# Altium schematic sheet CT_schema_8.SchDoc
size 401 x 301 mm
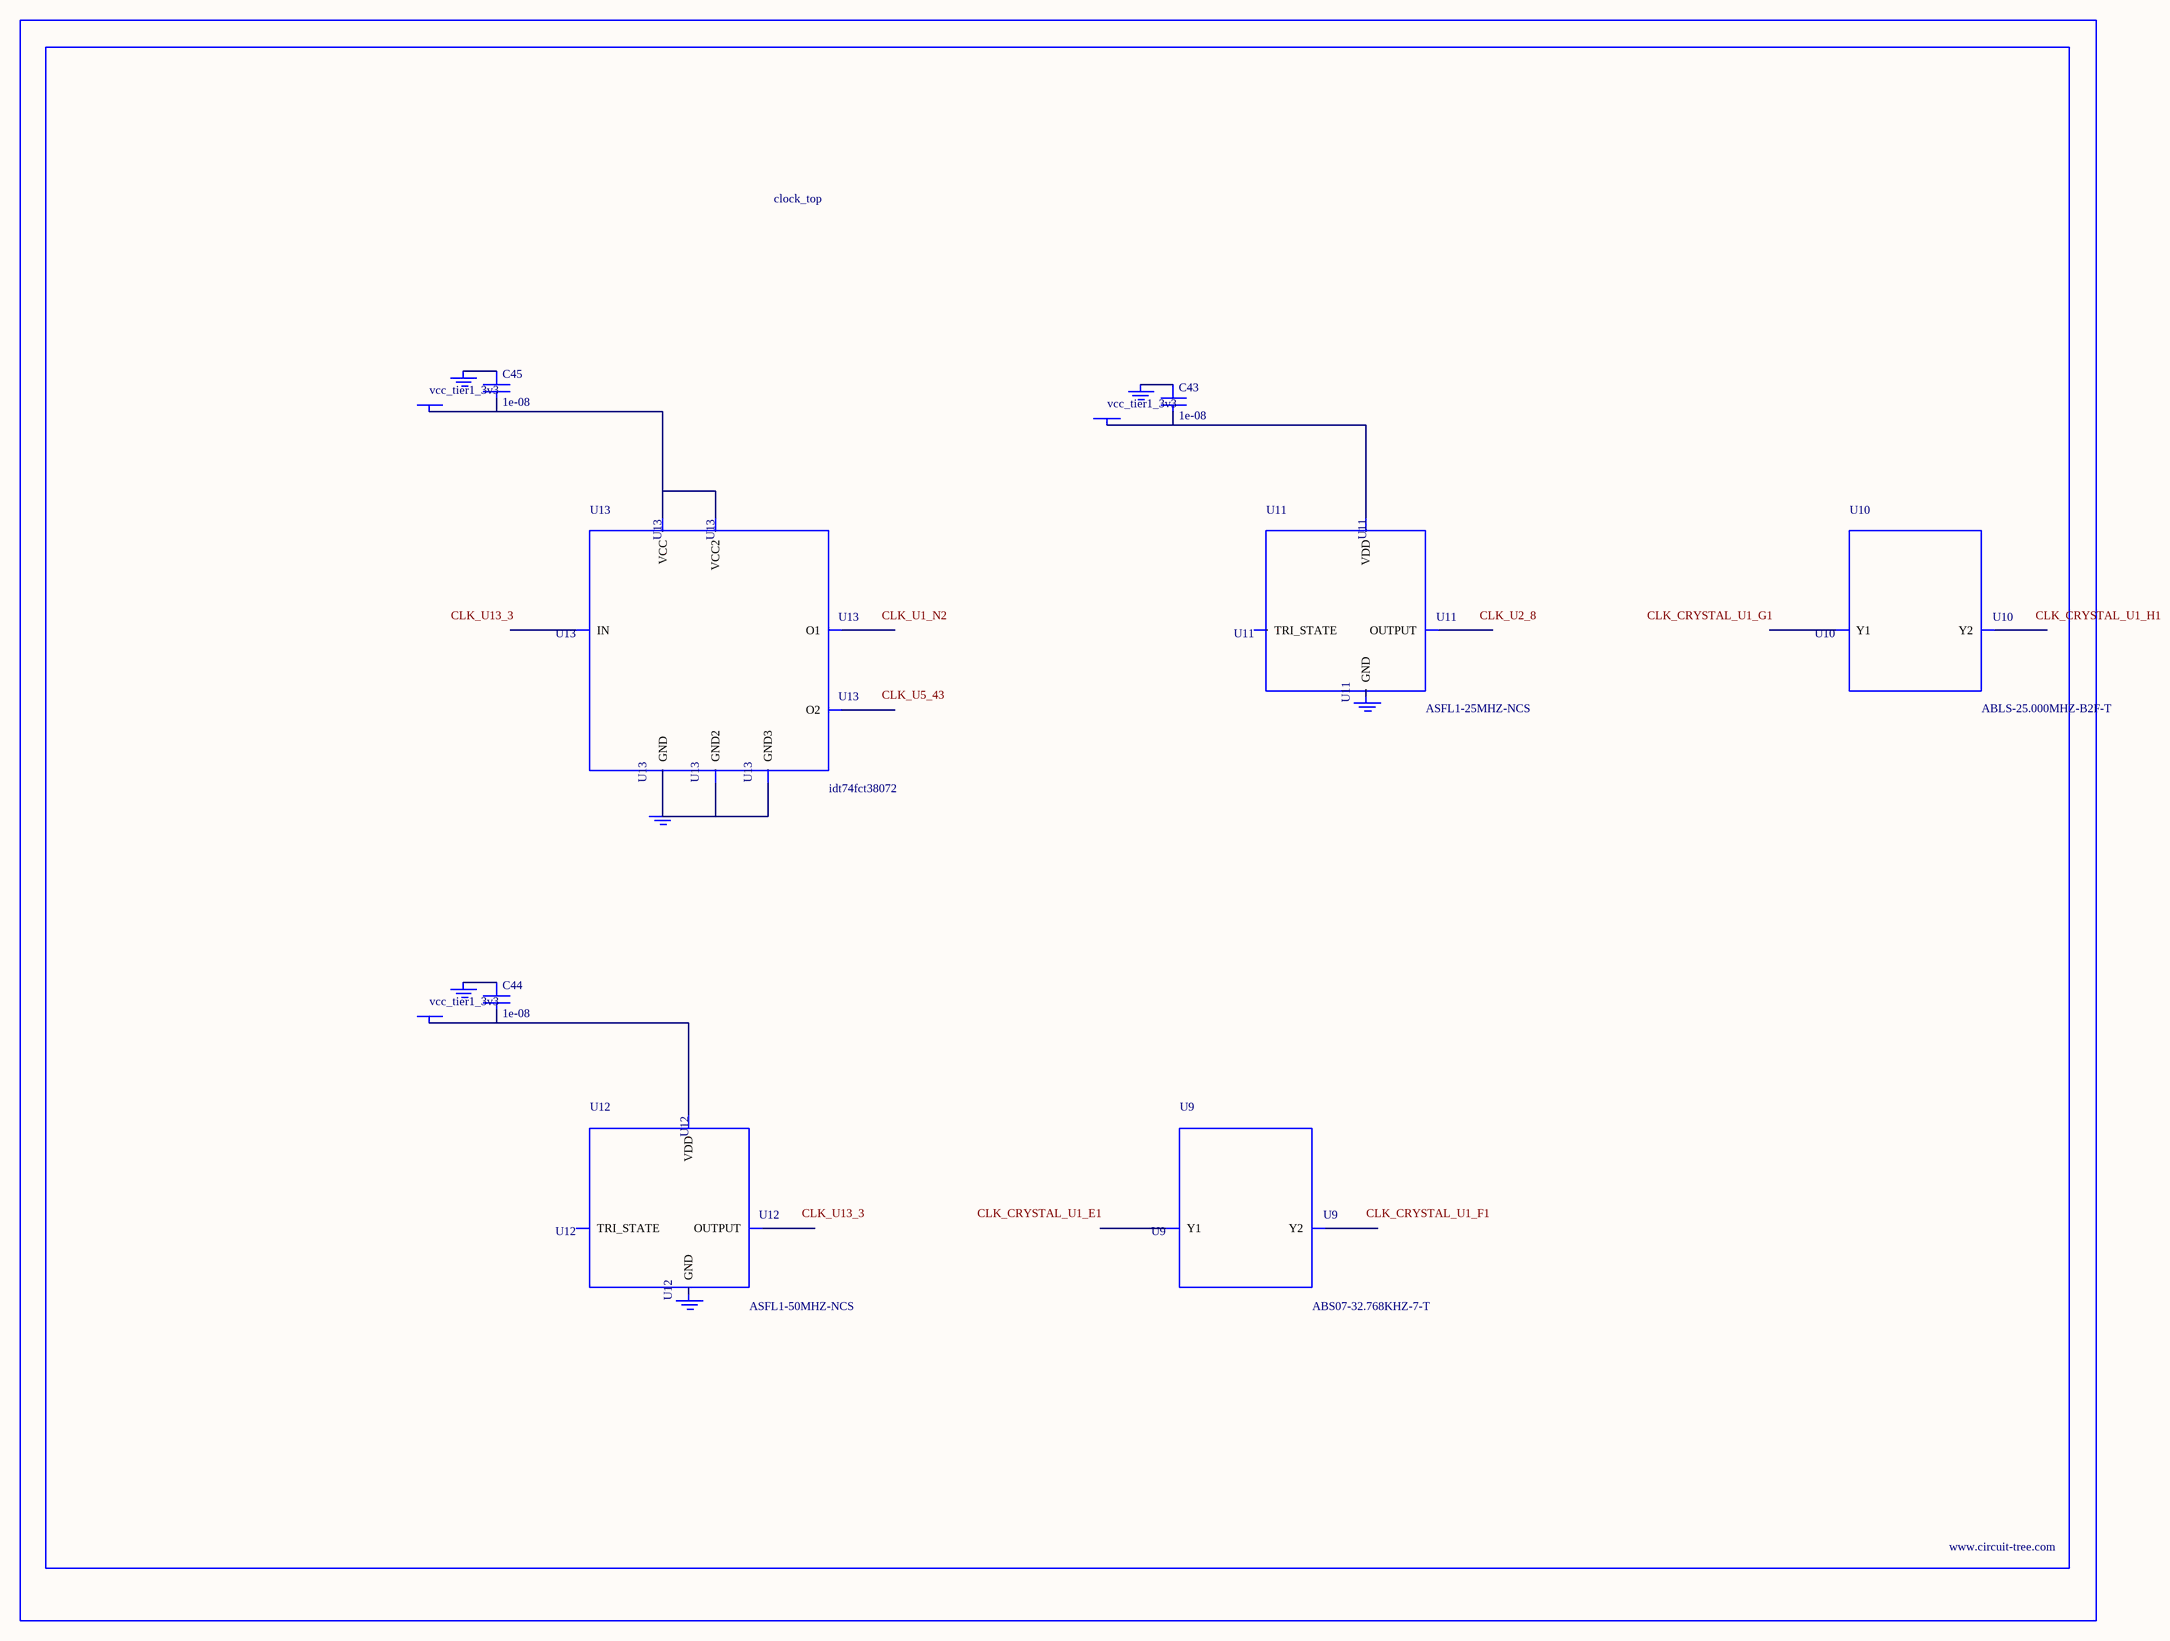
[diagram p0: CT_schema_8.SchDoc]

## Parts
BORDER7  (no value)
C43  1e-08  [C0402]
C44  1e-08  [C0402]
C45  1e-08  [C0402]
GND_INSTANCE_7_0  (no value)
GND_INSTANCE_7_1  (no value)
GND_INSTANCE_7_2  (no value)
GND_INSTANCE_7_3  (no value)
GND_INSTANCE_7_4  (no value)
GND_INSTANCE_7_5  (no value)
POWER_INSTANCE_7_0  vcc_tier1_3v3
POWER_INSTANCE_7_1  vcc_tier1_3v3
POWER_INSTANCE_7_2  vcc_tier1_3v3
U9  ABS07-32.768KHZ-7-T  [ABS07-32.768KHZ-7-T]
U10  ABLS-25.000MHZ-B2F-T  [ABLS-25.000MHZ-B2F-T]
U11  ASFL1-25MHZ-NCS  [ASFL1]
U12  ASFL1-50MHZ-NCS  [ASFL1]
U13  idt74fct38072  [IDT74FCT38072]

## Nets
NetC43_1: C43.1 GND_INSTANCE_7_0.0(GND)
NetC43_2: C43.2 POWER_INSTANCE_7_0.0(PWR) U11.4(VDD)
NetC44_1: C44.1 GND_INSTANCE_7_2.0(GND)
NetC44_2: C44.2 POWER_INSTANCE_7_1.0(PWR) U12.4(VDD)
NetC45_1: C45.1 GND_INSTANCE_7_4.0(GND)
NetC45_2: C45.2 POWER_INSTANCE_7_2.0(PWR) U13.1(VCC) U13.2(VCC2)
NetGND_INSTANCE_7_5_0: GND_INSTANCE_7_5.0(GND) U13.4(GND) U13.5(GND2) U13.8(GND3)

Not connected (* = marked no-connect by the designer): GND_INSTANCE_7_1 0(GND); GND_INSTANCE_7_3 0(GND); U9 1(Y1) 2(Y2); U10 1(Y1) 2(Y2); U11 1(TRI_STATE) 2(GND) 3(OUTPUT); U12 1(TRI_STATE) 2(GND) 3(OUTPUT); U13 3(IN) 6(O2) 7(O1)

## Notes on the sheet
- Labels drawn without touching a wire or pin: CLK_CRYSTAL_U1_E1, CLK_CRYSTAL_U1_F1, CLK_CRYSTAL_U1_G1, CLK_CRYSTAL_U1_H1, CLK_U1_N2, CLK_U2_8, CLK_U5_43, CLK_U13_3

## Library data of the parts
BORDER7 = BORDER_PAGE7
C43-C45 = C0402C103K3RAC
GND_INSTANCE_7_0-GND_INSTANCE_7_5 = GND
POWER_INSTANCE_7_0-POWER_INSTANCE_7_2 = PWR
